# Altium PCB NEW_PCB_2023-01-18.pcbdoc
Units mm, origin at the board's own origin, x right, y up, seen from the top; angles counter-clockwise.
Board outline 125.65 x 95.65 mm, 2 copper layers (Top Layer, Bottom Layer); 12 components, 94 nets, 156 pads, 2 vias.
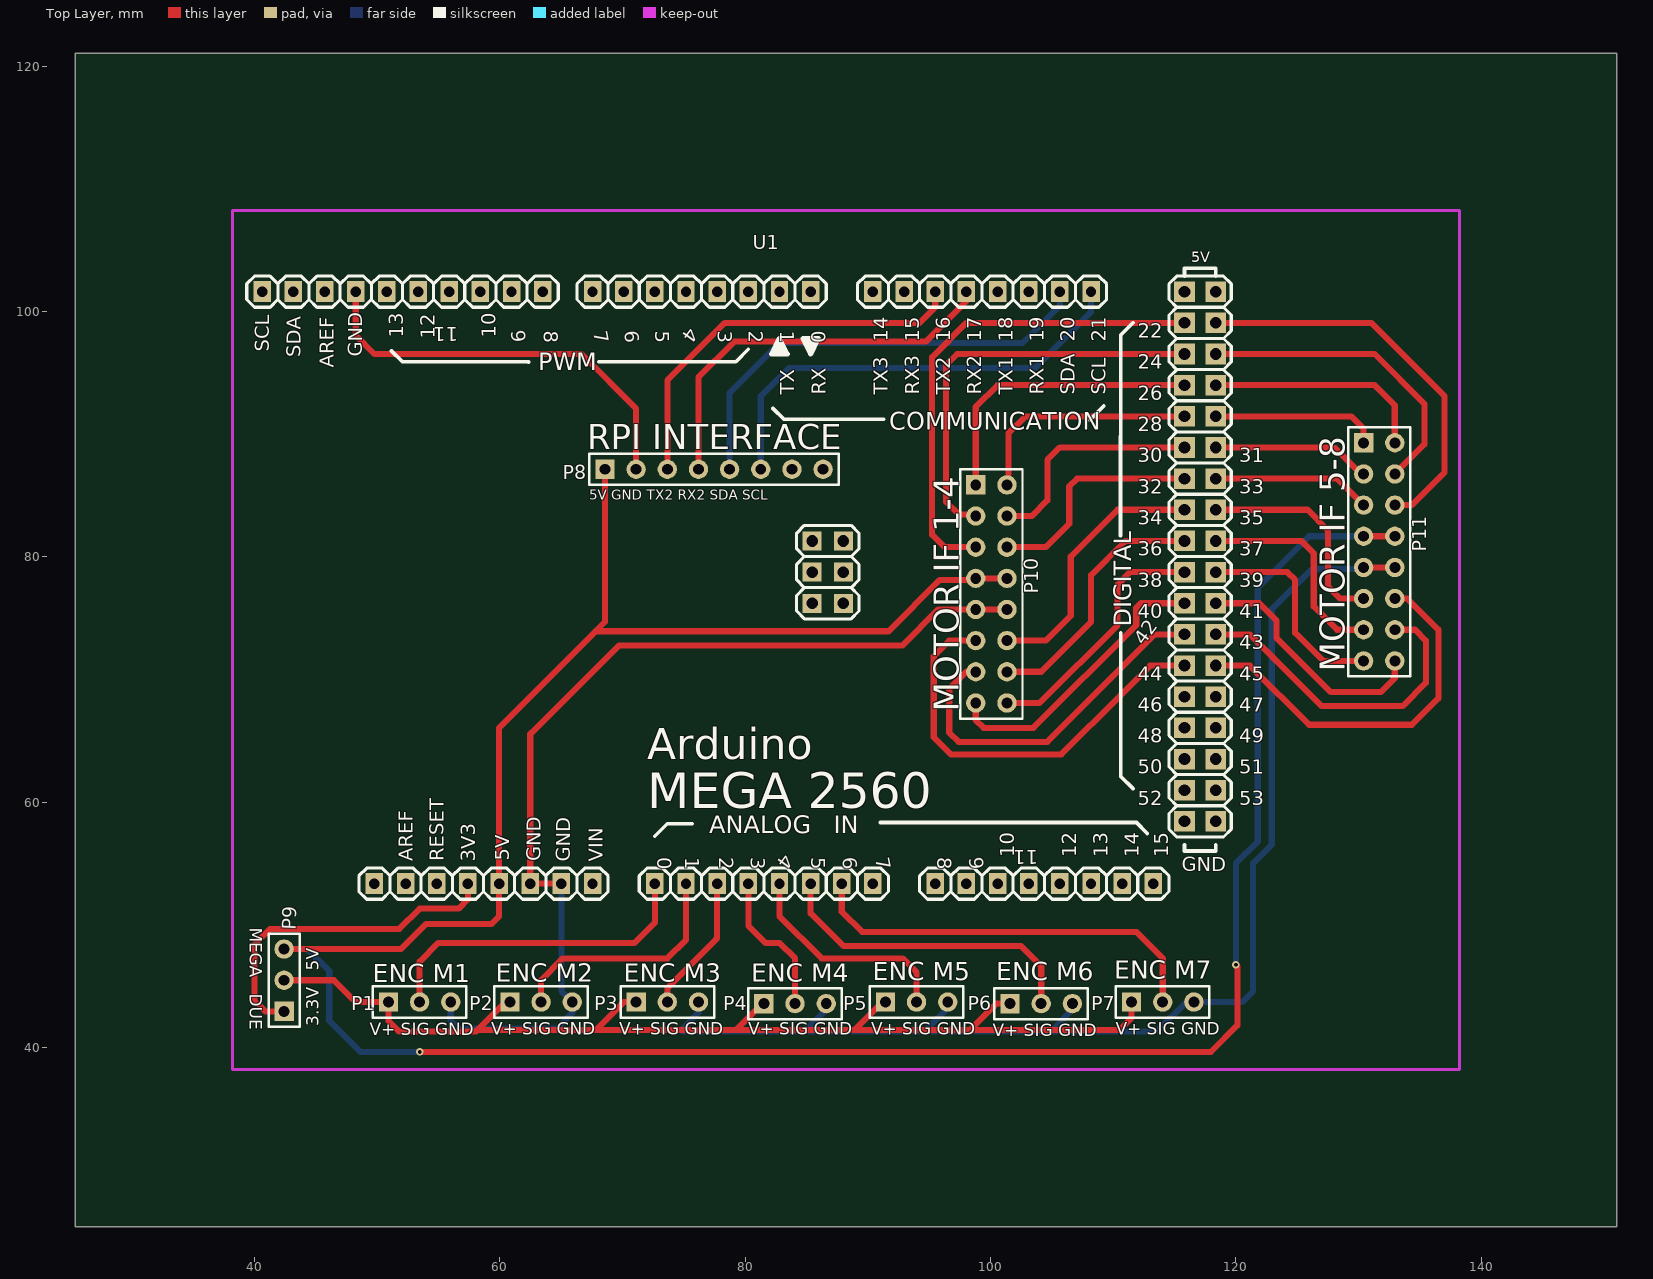
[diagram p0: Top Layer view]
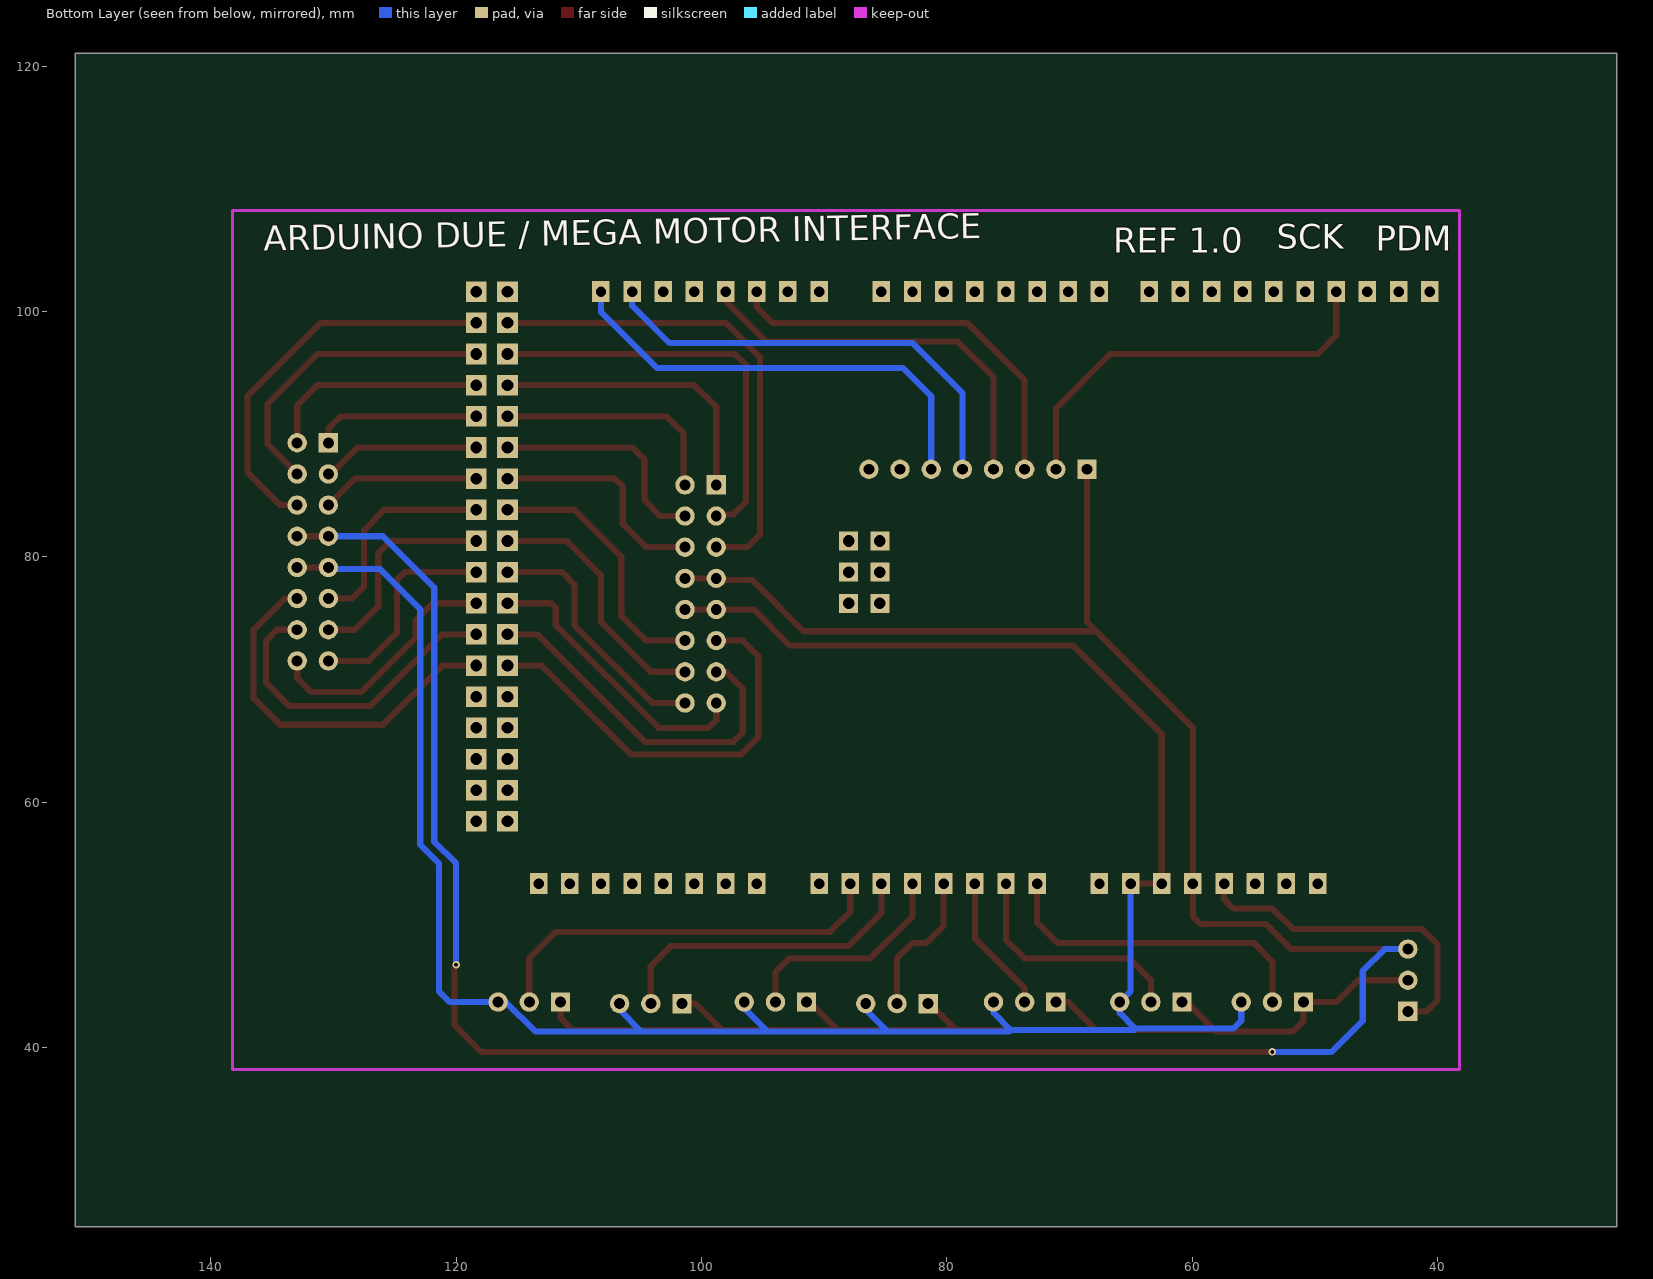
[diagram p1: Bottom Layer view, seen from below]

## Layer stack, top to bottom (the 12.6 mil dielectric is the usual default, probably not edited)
Top Layer: signal copper (thickness not stored)
Dielectric: dielectric 0.32, FR-4, Dk 4.8
Bottom Layer: signal copper (thickness not stored)

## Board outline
151.054,25.4 25.4,25.4 25.4,121.054 151.054,121.054

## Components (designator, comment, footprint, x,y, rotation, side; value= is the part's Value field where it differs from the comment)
P1 "Header-Male-2.54_1x3" HDR-3X1/2.54 53.467,43.711 r0 top
P2 "Header-Male-2.54_1x3" HDR-3X1/2.54 63.373,43.711 r0 top
P3 "Header-Male-2.54_1x3" HDR-3X1/2.54 73.66,43.711 r0 top
P4 "Header-Male-2.54_1x3" HDR-3X1/2.54 84.074,43.584 r0 top
P5 "Header-Male-2.54_1x3" HDR-3X1/2.54 93.98,43.711 r0 top
P6 "Header-Male-2.54_1x3" HDR-3X1/2.54 104.14,43.584 r0 top
P7 "Header-Male-2.54_1x3" HDR-3X1/2.54 114.046,43.711 r0 top
P8 "Header2.54mm 1*8P" HDR-8X1/2.54 77.47,87.145 r0 top
P9 "Header-Male-2.54_1x3" HDR-3X1/2.54 42.418,45.489 r90 top
P10 "Header-Male-2.54_2x8" HDR-8X2/2.54 100.076,76.985 r270 top
P11 "Header-Male-2.54_2x8" HDR-8X2/2.54 131.699,80.414 r270 top
U1 "oprokid_MEGA_2560" KIP_ARDUINO_MEGA_2560 -3245.485,-1259.309 r0 top

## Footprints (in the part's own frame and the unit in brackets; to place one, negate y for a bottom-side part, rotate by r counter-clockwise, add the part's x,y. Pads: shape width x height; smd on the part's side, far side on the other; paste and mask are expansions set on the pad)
HDR-3X1/2.54 [mil]
  rect 62x62 hole 35: 1(-100,0)
  round 62 hole 35: 2(0,0) 3(100,0)
  silkscreen extent -150,-50 150,50
HDR-8X1/2.54 [mil]
  rect 62x62 hole 35: 1(-350,0)
  round 62 hole 35: 2(-250,0) 3(-150,0) 4(-50,0) 5(50,0) 6(150,0) 7(250,0) 8(350,0)
  silkscreen extent -400,-50 400,50
HDR-8X2/2.54 [mil]
  rect 62x62 hole 35: 1(-350,-50)
  round 62 hole 35: 2(-350,50) 3(-250,-50) 4(-250,50) 5(-150,-50) 6(-150,50) 7(-50,-50) 8(-50,50) 9(50,-50) 10(50,50) 11(150,-50) 12(150,50) 13(250,-50) 14(250,50) 15(350,-50) 16(350,50)
  silkscreen extent -400,-100 400,100
KIP_ARDUINO_MEGA_2560 [mil]
  rect 56x67.2 hole 33.4: 1(129735,51680) 2(129835,51680) 3(129935,51680) 4(130035,51680) 5(130135,51680) 6(130235,51680) 6(130335,51680) 7(130435,51680) 8(130635,51680) 9(130735,51680) 10(130835,51680) 11(130935,51680) 12(131035,51680) 13(131135,51680) 14(131235,51680) 15(131335,51680) 16(131535,51680) 17(131635,51680) 18(131735,51680) 19(131835,51680) 20(131935,51680) 21(132035,51680) 22(132135,51680) 23(132235,51680) 24(132035,53580) 25(131935,53580) 26(131835,53580) 27(131735,53580) 28(131635,53580) 29(131535,53580) 30(131435,53580) 31(131335,53580) 32(131135,53580) 33(131035,53580) 34(130935,53580) 35(130835,53580) 36(130735,53580) 37(130635,53580) 38(130535,53580) 39(130435,53580) 40(130275,53580) 41(130175,53580) 42(130075,53580) 43(129975,53580) 44(129875,53580) 45(129775,53580) 46(129675,53580) 47(129575,53580) 48(129475,53580) 49(129375,53580)
  rect 66x66 hole 37.4: 50(132435,53580) 51(132435,53480) 52(132435,53380) 53(132435,53280) 54(132435,53180) 55(132435,53080) 56(132435,52980) 57(132435,52880) 58(132435,52780) 59(132435,52680) 60(132435,52580) 61(132435,52480) 62(132435,52380) 63(132435,52280) 64(132435,52180) 65(132435,52080) 66(132435,51980) 67(132435,51880) 68(132335,53580) 69(132335,53480) 70(132335,53380) 71(132335,53280) 72(132335,53180) 73(132335,53080) 74(132335,52980) 75(132335,52880) 76(132335,52780) 77(132335,52680) 78(132335,52580) 79(132335,52480) 80(132335,52380) 81(132335,52280) 82(132335,52180) 83(132335,52080) 84(132335,51980) 85(132335,51880)
  rect 61x61 hole 37.4: 96(131240,52780) 97(131240,52680) 98(131240,52580) 99(131140,52780) 100(131140,52680) 101(131140,52580)
  silkscreen extent 129325,51630 132485,53655

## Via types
v1: diameter 0.62, hole 0.305, Top Layer to Bottom Layer, tented both sides, 2 vias

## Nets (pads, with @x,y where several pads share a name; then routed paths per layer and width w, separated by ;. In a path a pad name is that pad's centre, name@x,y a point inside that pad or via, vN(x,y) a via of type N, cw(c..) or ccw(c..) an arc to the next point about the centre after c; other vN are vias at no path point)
+5V: P8.1 P9.3 P10.7 P10.8 P11.7 P11.8 U1.5 | length 227.8
  Top Layer w0.5: P9.3 51.943,48.029 53.975,50.061 59.309,50.061 59.944,50.696 U1.5 59.944,66.063 67.818,73.937 ; v1(53.467,39.647) 117.983,39.647 120.142,41.806 120.142,46.632 v1(120.015,46.759) ; P8.1 68.58,74.699 67.818,73.937 ; P10.8 P10.7 98.679,78.128 95.885,78.128 91.694,73.937 67.818,73.937 ; P11.7 P11.8
  Bottom Layer w0.5: P9.3 44.323,48.029 46.101,46.251 46.101,42.187 48.641,39.647 v1(53.467,39.647) ; v1(120.015,46.759) 120.015,55.014 121.793,56.792 121.793,77.493 125.984,81.684 P11.7
GND: P1.3 P2.3 P3.3 P4.3 P5.3 P6.3 P7.3 P10.9 P10.10 P11.9 P11.10 U1.6 | length 194.5
  Top Layer w0.5: U1.6@65.024,53.363 62.484,53.363 62.484,65.555 62.611,65.682 69.723,72.794 92.837,72.794 95.758,75.715 P10.9 P10.10 ; P11.9 P11.10
  Bottom Layer w0.5: P1.3 56.007,42.187 56.642,41.552 64.643,41.552 ; U1.6@65.024,53.363 65.024,44.6 P2.3 65.913,42.822 64.643,41.552 ; P3.3 76.2,42.822 74.803,41.425 ; P4.3 86.614,43.076 84.836,41.298 ; P5.3 96.52,43.203 94.615,41.298 ; P6.3 106.68,43.076 104.902,41.298 ; P11.9 130.302,79.017 126.238,79.017 122.936,75.715 122.936,56.538 121.412,55.014 121.412,44.6 120.523,43.711 P7.3 115.951,43.711 113.538,41.298 104.902,41.298 ; 64.643,41.552 64.77,41.425 74.803,41.425 ; 74.803,41.425 74.93,41.298 84.836,41.298 ; 84.836,41.298 94.615,41.298 ; 94.615,41.298 104.902,41.298
P1_1: P1.1 P2.1 P3.1 P4.1 P5.1 P6.1 P7.1 P9.2 | length 92.7
  Top Layer w0.5: P9.2 46.482,45.489 48.26,43.711 P1.1 50.927,42.187 51.816,41.298 58.039,41.298 ; P2.1 60.452,43.711 58.039,41.298 ; P3.1 70.104,43.711 67.818,41.425 ; 78.955,41.425 88.9,41.425 ; P4.1 81.407,43.584 80.391,42.568 79.248,41.425 67.818,41.425 ; P5.1 91.186,43.711 88.9,41.425 ; P6.1 100.457,43.584 98.298,41.425 ; P7.1 111.506,42.441 110.49,41.425 98.298,41.425 ; 58.039,41.298 58.166,41.425 67.818,41.425 ; 88.9,41.425 98.298,41.425
P8_7: P8.7
P8_8: P8.8
U1_1: U1.1
U1_2: U1.2
U1_3: U1.3
U1_4: P9.1 U1.4 | length 27.5
  Top Layer w0.5: P9.1 40.894,42.949 40.005,43.838 40.005,48.41 41.275,49.68 51.816,49.68 53.467,51.331 56.642,51.331 57.404,52.093 U1.4
U1_7: U1.7
U1_8: P1.2 U1.8 | length 27
  Top Layer w0.5: P1.2 53.467,47.013 54.991,48.537 70.993,48.537 72.644,50.188 U1.8
U1_9: P2.2 U1.9 | length 19.5
  Top Layer w0.5: P2.2 63.373,45.489 65.151,47.267 73.66,47.267 75.184,48.791 U1.9
U1_10: P3.2 U1.10 | length 11.3
  Top Layer w0.5: P3.2 73.66,44.854 77.597,48.791 77.724,48.918 U1.10
U1_11: P4.2 U1.11 | length 12
  Top Layer w0.5: U1.11 80.264,49.934 81.661,48.537 82.804,48.537 84.074,47.267 P4.2
U1_12: P5.2 U1.12 | length 18.1
  Top Layer w0.5: U1.12 82.804,50.696 86.233,47.267 92.837,47.267 93.98,46.124 P5.2
U1_13: P6.2 U1.13 | length 26
  Top Layer w0.5: U1.13 85.344,50.95 88.011,48.283 102.489,48.283 104.14,46.632 P6.2
U1_14: P7.2 U1.14 | length 33.6
  Top Layer w0.5: U1.14 87.884,51.077 89.535,49.426 111.887,49.426 114.046,47.267 P7.2
U1_15: U1.15
U1_16: U1.16
U1_17: U1.17
U1_18: U1.18
U1_19: U1.19
U1_20: U1.20
U1_21: U1.21
U1_22: U1.22
U1_23: U1.23
U1_24: P8.6 U1.24 | length 37.4
  Bottom Layer w0.5: P8.6 81.28,93.114 83.566,95.4 103.632,95.4 108.204,99.972 U1.24
U1_25: P8.5 U1.25 | length 37.2
  Bottom Layer w0.5: P8.5 78.74,93.368 82.804,97.432 102.616,97.432 105.664,100.48 U1.25
U1_26: U1.26
U1_27: U1.27
U1_28: P8.4 U1.28 | length 32.7
  Top Layer w0.5: P8.4 76.2,94.638 79.121,97.559 94.742,97.559 97.917,100.734 98.044,100.861 U1.28
U1_29: P8.3 U1.29 | length 32.8
  Top Layer w0.5: P8.3 73.66,94.384 78.359,99.083 94.234,99.083 95.504,100.353 U1.29
U1_30: U1.30
U1_31: U1.31
U1_32: U1.32
U1_33: U1.33
U1_34: U1.34
U1_35: U1.35
U1_36: U1.36
U1_37: U1.37
U1_38: U1.38
U1_39: U1.39
U1_40: U1.40
U1_41: U1.41
U1_42: U1.42
U1_43: U1.43
U1_44: U1.44
U1_45: U1.45
U1_46: P8.2 U1.46 | length 33.8
  Top Layer w0.5: U1.46 48.26,98.067 49.784,96.543 66.675,96.543 71.12,92.098 P8.2
U1_47: U1.47
U1_48: U1.48
U1_49: U1.49
U1_50: U1.50
U1_51: P11.6 U1.51 | length 32.5
  Top Layer w0.5: U1.51 131.064,99.083 137.033,93.114 137.033,86.891 134.366,84.224 P11.6
U1_52: P11.4 U1.52 | length 25.4
  Top Layer w0.5: U1.52 131.318,96.543 135.382,92.479 135.382,89.177 P11.4
U1_53: P11.2 U1.53 | length 18.3
  Top Layer w0.5: U1.53 131.318,94.003 131.445,93.876 132.969,92.352 P11.2
U1_54: P11.1 U1.54 | length 13.6
  Top Layer w0.5: U1.54 129.413,91.463 130.429,90.447 P11.1
U1_55: P11.3 U1.55 | length 13
  Top Layer w0.5: U1.55 128.016,88.923 130.175,86.764 P11.3
U1_56: P11.5 U1.56 | length 13
  Top Layer w0.5: U1.56 128.27,86.383 P11.5
U1_57: P11.11 U1.57 | length 17.7
  Top Layer w0.5: U1.57 125.857,83.843 127.508,82.192 127.508,77.62 128.524,76.604 P11.11
U1_58: P11.13 U1.58 | length 17.6
  Top Layer w0.5: U1.58 125.349,81.303 126.365,80.287 126.365,75.969 128.27,74.064 P11.13
U1_59: P11.15 U1.59 | length 17.6
  Top Layer w0.5: U1.59 124.206,78.763 124.841,78.128 124.841,73.81 127.127,71.524 P11.15
U1_60: P11.16 U1.60 | length 20.3
  Top Layer w0.5: U1.60 121.92,76.223 123.317,74.826 123.317,73.429 127.762,68.984 131.826,68.984 132.969,70.127 P11.16
U1_61: P11.14 U1.61 | length 26.7
  Top Layer w0.5: U1.61 121.158,73.683 121.92,72.921 127,67.841 133.604,67.841 135.509,69.746 135.509,73.175 134.62,74.064 P11.14
U1_62: P11.12 U1.62 | length 31.3
  Top Layer w0.5: U1.62 121.158,71.143 125.984,66.317 134.366,66.317 136.525,68.476 136.525,74.064 133.985,76.604 P11.12
U1_63: U1.63
U1_64: U1.64
U1_65: U1.65
U1_66: U1.66
U1_67: U1.67
U1_68: U1.68
U1_69: P10.5 U1.69 | length 40.2
  Top Layer w0.5: P10.5 96.266,80.795 95.25,81.811 95.25,96.289 98.044,99.083 U1.69
U1_70: P10.3 U1.70 | length 33.9
  Top Layer w0.5: P10.3 98.679,83.462 97.409,83.462 96.393,84.478 96.393,95.654 97.282,96.543 U1.70
U1_71: P10.1 U1.71 | length 24.1
  Top Layer w0.5: P10.1 98.806,92.225 100.584,94.003 U1.71
U1_72: P10.2 U1.72 | length 19.2
  Top Layer w0.5: P10.2 101.473,86.002 101.473,90.066 102.87,91.463 U1.72
U1_73: P10.4 U1.73 | length 18.7
  Top Layer w0.5: P10.4 103.378,83.335 104.648,84.605 104.648,87.907 105.664,88.923 U1.73
U1_74: P10.6 U1.74 | length 18.6
  Top Layer w0.5: P10.6 104.521,80.795 106.426,82.7 106.426,85.748 107.061,86.383 U1.74
U1_75: P10.12 U1.75 | length 21.7
  Top Layer w0.5: P10.12 104.521,73.175 106.553,75.207 106.553,80.033 110.363,83.843 U1.75
U1_76: P10.14 U1.76 | length 21.1
  Top Layer w0.5: P10.14 104.14,70.635 108.204,74.699 108.204,78.509 110.871,81.176 110.998,81.303 U1.76
U1_77: P10.16 U1.77 | length 20.8
  Top Layer w0.5: P10.16 104.013,68.095 110.363,74.445 110.363,77.747 111.379,78.763 U1.77
U1_78: P10.15 U1.78 | length 23.7
  Top Layer w0.5: P10.15 98.806,66.698 99.441,66.063 103.505,66.063 111.887,74.445 111.887,75.842 112.268,76.223 U1.78
U1_79: P10.13 U1.79 | length 29.4
  Top Layer w0.5: P10.13 98.044,70.635 96.647,69.238 96.647,65.682 97.409,64.92 104.648,64.92 113.411,73.683 U1.79
U1_80: P10.11 U1.80 | length 34.6
  Top Layer w0.5: P10.11 96.647,73.175 95.377,71.905 95.377,65.301 96.774,63.904 105.791,63.904 110.617,68.73 113.03,71.143 U1.80
U1_81: U1.81
U1_82: U1.82
U1_83: U1.83
U1_84: U1.84
U1_85: U1.85
U1_96: U1.96
U1_97: U1.97
U1_98: U1.98
U1_99: U1.99
U1_100: U1.100
U1_101: U1.101

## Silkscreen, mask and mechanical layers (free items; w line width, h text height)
Top Overlay:
  text "RPI INTERFACE" at 67.125,88.796 h2.03
  text "5V GND TX2 RX2 SDA SCL" at 67.31,84.657 h0.8
  text "MOTOR IF 5-8" at 128.905,70.635 h2.03 r90
  text "MOTOR IF 1-4" at 97.409,67.369 h2.03 r90
  text "MEGA   DUE" at 39.632,49.769 h1 r270
  text "ENC M7" at 110.109,45.628 h1.5
  text "ENC M5" at 90.424,45.501 h1.5
  text "ENC M6" at 100.457,45.501 h1.5
  text "ENC M2" at 59.69,45.374 h1.5
  text "ENC M3" at 70.104,45.374 h1.5
  text "ENC M4" at 80.518,45.374 h1.5
  text "ENC M1" at 49.657,45.318 h1.5
  text "3.3V   5V" at 45.242,41.737 h1 r90
  text "V+ SIG GND" at 59.309,41.052 h1
  text "V+ SIG GND" at 69.723,41.052 h1
  text "V+ SIG GND" at 80.264,41.052 h1
  text "V+ SIG GND" at 90.297,41.052 h1
  text "V+ SIG GND" at 110.236,41.052 h1
  text "V+ SIG GND" at 49.403,41.014 h1
  text "V+ SIG GND" at 100.203,40.925 h1
Bottom Overlay:
  text "SCK" at 53.115,105.12 h2
  text "ARDUINO DUE / MEGA MOTOR INTERFACE" at 135.704,104.971 h2.03 r359
  text "PDM" at 45.034,104.96 h2.03
  text "REF 1.0" at 66.421,104.798 h2.03
Document:
  lines w0.003: 88.227,73.227 88.227,73.227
